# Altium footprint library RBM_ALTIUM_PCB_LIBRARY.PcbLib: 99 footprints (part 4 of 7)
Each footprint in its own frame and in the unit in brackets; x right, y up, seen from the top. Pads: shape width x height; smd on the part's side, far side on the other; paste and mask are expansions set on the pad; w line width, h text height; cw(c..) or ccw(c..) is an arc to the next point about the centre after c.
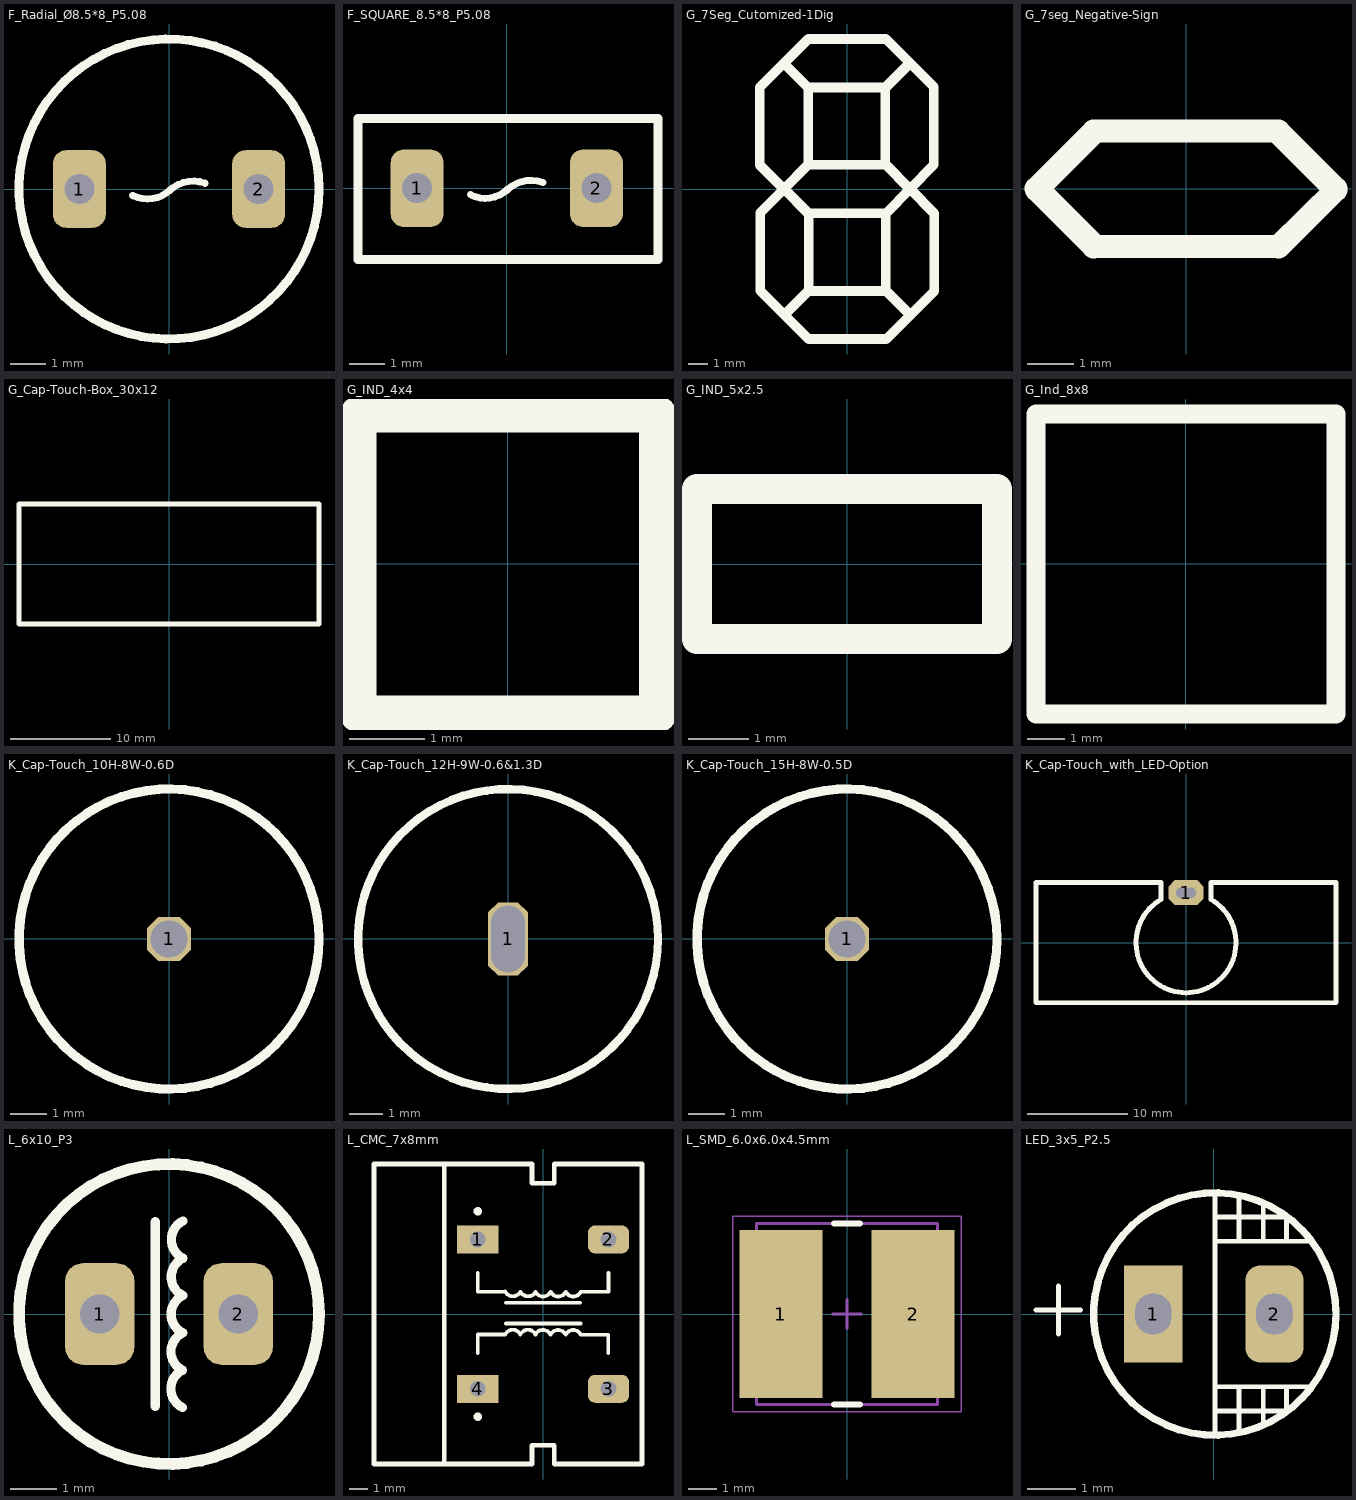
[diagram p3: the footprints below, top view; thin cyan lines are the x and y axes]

## F_Radial_Ø8.5*8_P5.08 [mm] "37011000000; Through Hole,P=5.08mm Fuses with Leads (Through Hole) RoHS"
pads (2):
  rrect50% 1.5x2.2 hole 0.85: 1(-2.54,0) 2(2.54,0)
Top Overlay:
  lines w0.2: -1.028,-0.184 ccw(c-0.609,0.633) 0.034,-0.022 ; 0.001,-0.057 cw(c0.685,-0.753) 1.023,0.162
  lines w0.254: 4.25,0 cw(c0,0) 4.25,0.019
3D body "User Library-Fuísivel 37200500411.step": height 8, standoff -4.3, extent -4.25,-4.25 4.25,4.25

## F_SQUARE_8.5*8_P5.08 [mm] "Littelfuse 39211000440; TE5 Time-Lag Fuse"
pads (2):
  rrect50% 1.5x2.2 hole 0.85: 1(-2.54,0) 2(2.54,0)
Top Overlay:
  lines w0.2: -1.028,-0.184 ccw(c-0.609,0.633) 0.034,-0.022 ; 0.001,-0.057 cw(c0.685,-0.753) 1.023,0.162
  lines w0.254: -4.216,-2.022 4.284,-2.022 4.284,1.978 -4.216,1.978 -4.216,-2.022
3D body "User Library-A3D-008-00001.step": height 8, standoff -3, extent -4.216,-2.022 4.284,1.978

## G_7Seg_Cutomized-1Dig [mm]
Top Overlay:
  lines w0.5: -4.475,1.237 -3.237,0 ; -3.263,0 -4.5,1.237 -4.5,5.237 -3.263,6.475 ; -3.237,6.5 -2,7.737 2,7.737 3.237,6.5 4.475,5.263 4.475,1.263 3.237,0.025 ; -3.212,-6.475 -1.975,-5.237 2.025,-5.237 3.263,-6.475 ; -3.212,-6.45 -1.975,-5.212 -1.975,-1.212 -3.212,0.025 ; -2,-7.687 -3.237,-6.45 -4.475,-5.212 -4.475,-1.212 -3.237,0.025 ; -2,-1.212 -3.237,0.025 ; -2,7.712 -3.237,6.475 ; -1.975,-7.712 2.025,-7.712 3.263,-6.475 ; 3.212,0.025 1.975,1.263 1.975,5.263 3.212,6.5 ; 3.237,-6.475 2,-5.237 2,-1.237 ; 3.237,6.475 2,5.237 -2,5.237 ; 3.263,0 4.5,-1.237 4.5,-5.237 3.263,-6.475 ; 4.475,-1.237 3.237,0 ; -3.237,0 -2,-1.237 2,-1.237 ; -3.237,0 -2,1.237 ; -3.237,0 -2,1.237 ; -3.237,0.025 -2,1.263 2,1.263 ; -3.237,6.475 -2,5.237 ; -3.237,6.475 -2,5.237 ; -2,1.237 -2,5.237 ; 2,-1.237 3.237,0 ; 2,-1.237 3.237,0 ; 2,1.263 3.237,0.025 ; 2,1.263 3.237,0.025
3D body: height 8, standoff 0, extent -3.511,-0.238 -1.767,1.506
3D body: height 8, standoff 0, extent -3.515,-1.478 -1.772,0.265
3D body: height 8, standoff 0, extent 1.748,-1.487 3.492,0.257
3D body: height 8, standoff 0, extent -2.25,1 2.238,1.5
3D body: height 8, standoff 0, extent 1.753,-0.247 3.497,1.497
3D body: height 8, standoff 0, extent -2.25,-1.5 2.238,-1
3D body: height 8, standoff 0, extent 1.759,-0.305 3.503,1.439
3D body: height 8, standoff 0, extent 3,-0.309 4.743,1.435
3D body: height 8, standoff 0, extent 3.008,4.954 4.752,6.698
3D body: height 8, standoff 0, extent 1.765,0.956 2.265,5.444
3D body: height 8, standoff 0, extent 1.768,4.959 3.511,6.703
3D body: height 8, standoff 0, extent 4.265,0.956 4.765,5.444
3D body: height 8, standoff 0, extent 1.757,-6.711 3.501,-4.967
3D body: height 8, standoff 0, extent 2.997,-6.715 4.741,-4.972
3D body: height 8, standoff 0, extent 3.006,-1.452 4.749,0.292
3D body: height 8, standoff 0, extent 1.763,-5.45 2.263,-0.962
3D body: height 8, standoff 0, extent 1.765,-1.447 3.509,0.297
3D body: height 8, standoff 0, extent 4.263,-5.45 4.763,-0.962
3D body: height 8, standoff 0, extent 1.773,-7.956 3.517,-6.212
3D body: height 8, standoff 0, extent 1.778,-6.715 3.522,-4.971
3D body: height 8, standoff 0, extent -3.486,-6.707 -1.742,-4.963
3D body: height 8, standoff 0, extent -2.232,-7.95 2.256,-7.45
3D body: height 8, standoff 0, extent -3.49,-7.947 -1.747,-6.203
3D body: height 8, standoff 0, extent -2.232,-5.45 2.256,-4.95
3D body: height 8, standoff 0, extent -3.466,-1.433 -1.722,0.311
3D body: height 8, standoff 0, extent -4.706,-1.428 -2.963,0.315
3D body: height 8, standoff 0, extent -4.715,-6.692 -2.971,-4.948
3D body: height 8, standoff 0, extent -2.228,-5.438 -1.728,-0.95
3D body: height 8, standoff 0, extent -3.475,-6.697 -1.731,-4.953
3D body: height 8, standoff 0, extent -4.728,-5.438 -4.228,-0.95
3D body: height 8, standoff 0, extent -3.494,4.967 -1.75,6.711
3D body: height 8, standoff 0, extent -4.735,4.972 -2.991,6.715
3D body: height 8, standoff 0, extent -4.743,-0.292 -2.999,1.452
3D body: height 8, standoff 0, extent -2.256,0.962 -1.756,5.45
3D body: height 8, standoff 0, extent -3.503,-0.297 -1.759,1.447
3D body: height 8, standoff 0, extent -4.756,0.962 -4.256,5.45
3D body: height 8, standoff 0, extent 1.767,4.994 3.511,6.738
3D body: height 8, standoff 0, extent 1.772,6.235 3.515,7.978
3D body: height 8, standoff 0, extent -3.492,6.243 -1.748,7.987
3D body: height 8, standoff 0, extent -2.238,5 2.25,5.5
3D body: height 8, standoff 0, extent -3.497,5.003 -1.753,6.747
3D body: height 8, standoff 0, extent -2.238,7.5 2.25,8

## G_7seg_Negative-Sign [mm]
Top Overlay:
  lines w0.5: -3.237,0 -2,1.237 ; -3.212,0 -1.975,-1.237 ; -2,-1.263 -3.237,-0.025 -2,1.212 ; 1.975,1.237 3.212,0 ; 2,-1.263 3.25,-0.025 ; 2,-1.25 -2,-1.25 -3.25,0 -2,1.25 2,1.25 3.25,0 ; 2,1.237 3.237,0
3D body: height 8, standoff 0, extent 1.767,-1.506 3.511,0.238
3D body: height 8, standoff 0, extent 1.772,-0.265 3.515,1.478
3D body: height 8, standoff 0, extent -3.492,-0.257 -1.748,1.487
3D body: height 8, standoff 0, extent -2.238,-1.5 2.25,-1
3D body: height 8, standoff 0, extent -3.497,-1.497 -1.753,0.247
3D body: height 8, standoff 0, extent -2.244,1 2.244,1.5

## G_Cap-Touch-Box_30x12 [mm]
Top Overlay:
  lines w0.5: -15,-6 15,-6 15,6 -15,6 -15,-6
3D body: height 8, standoff 0, extent -15.25,-6.206 -14.75,6.207
3D body: height 8, standoff 0, extent -15.206,-6.25 15.207,-5.75
3D body: height 8, standoff 0, extent 14.75,-6.206 15.25,6.207
3D body: height 8, standoff 0, extent -15.206,5.75 15.207,6.25

## G_IND_4x4 [mm]
Top Overlay:
  lines w0.5: -2,-2 -2,2 2,2 2,-2 -2,-2
3D body: height 8, standoff 0, extent -2.256,1.75 2.257,2.25
3D body: height 8, standoff 0, extent -2.25,-2.257 -1.75,2.256
3D body: height 8, standoff 0, extent -2.263,-2.25 2.25,-1.75
3D body: height 8, standoff 0, extent 1.75,-2.256 2.25,2.257

## G_IND_5x2.5 [mm]
Top Overlay:
  lines w0.5: -2.506,-1.244 -2.506,1.256 2.494,1.256 2.494,-1.244 -2.506,-1.244
3D body: height 8, standoff 0, extent 2.244,-1.48 2.744,1.492
3D body: height 8, standoff 0, extent -2.74,-1.494 2.727,-0.994
3D body: height 8, standoff 0, extent -2.756,-1.48 -2.256,1.492
3D body: height 8, standoff 0, extent -2.739,1.006 2.728,1.506

## G_Ind_8x8 [mm]
Top Overlay:
  lines w0.5: -3.994,-4.006 4.006,-4.006 4.006,3.994 -3.994,3.994 -3.994,-4.006
3D body: height 8, standoff 0, extent 3.756,-4.241 4.256,4.229
3D body: height 8, standoff 0, extent -4.229,-4.256 4.241,-3.756
3D body: height 8, standoff 0, extent -4.244,-4.241 -3.744,4.228
3D body: height 8, standoff 0, extent -4.228,3.744 4.241,4.244

## K_Cap-Touch_10H-8W-0.6D [mm]
pads (1):
  oct 1.2x1.2 / inner oct 1x1 / far side oct 2.5x2.5 hole 1: 1(0,0)
Top Overlay:
  circle w0.254: c0,0 r4.09
3D body: height 3, standoff -3, extent -0.258,-0.259 0.26,0.26
3D body: height 10, standoff 0, extent -4,-3.997 4,3.997

## K_Cap-Touch_12H-9W-0.6&1.3D [mm]
pads (1):
  oct 1.2x2.2 / inner oct 1x1 / far side oct 3x3 hole 2 slot 1 at 0 deg: 1(0,0)
Top Overlay:
  circle w0.254: c0,0 r4.5
3D body: height 12, standoff 0, extent -4.5,-4.5 4.5,4.5
3D body: height 5, standoff -3, extent -0.3,-0.7 0.3,0.7

## K_Cap-Touch_15H-8W-0.5D [mm]
pads (1):
  oct 1.2x1.2 / inner oct 1x1 / far side oct 2.5x2.5 hole 1: 1(0,0)
Top Overlay:
  circle w0.254: c0,0 r4.09
3D body: height 3, standoff -3, extent -0.258,-0.259 0.26,0.26
3D body: height 15, standoff 0, extent -4,-3.997 4,3.997

## K_Cap-Touch_with_LED-Option [mm]
pads (1):
  oct 3.5x2.5 hole 2 slot 1 at 90 deg: 1(0,5)
Top Overlay:
  lines w0.5: -15,-6 15,-6 15,6 2.5,6 2.5,4.33 cw(c0,0) -2.5,4.33 -2.5,6 -15,6 -15,-6
3D body "Touch_Spring.STEP": height 11.25, standoff -2.76, extent -5.25,-5.25 5.25,5.25

## L_6x10_P3 [mm]
pads (2):
  rrect50% 1.5x2.2 hole 0.85: 1(-1.5,0) 2(1.5,0)
Top Overlay:
  circle w0.254: c0,0 r3.25
  lines w0.2: -0.3,-2 -0.3,2 ; 0.293,-2.025 cw(c0.489,-1.622) 0.295,-1.217 cw(c0.492,-0.813) 0.298,-0.408 cw(c0.494,-0.005) 0.3,0.4 cw(c0.497,0.804) 0.302,1.208 cw(c0.499,1.612) 0.305,2.017
3D body: height 11.5, standoff 0.5, extent -2.993,-3.07 3.006,2.93
3D body: height 3.25, standoff 0.25, extent -3.242,-3.316 3.258,3.177
3D body: height 13, standoff 10, extent -3.242,-3.316 3.258,3.177
3D body: height 2, standoff -1, extent -1.799,-0.299 -1.201,0.299
3D body: height 2, standoff -1, extent 1.202,-0.299 1.8,0.3

## L_CMC_7x8mm [mm] "UU9.8"
pads (4):
  rect 2.2x1.5 hole 0.85: 1(-3.501,3.996) 4(-3.501,-4.004)
  rrect50% 2.2x1.5 hole 0.85: 2(3.499,3.996) 3(3.499,-4.004)
Top Overlay:
  lines w0.2: -3.501,-2.104 -3.501,-1.096 -2.026,-1.096 cw(c-1.622,-1.293) -1.218,-1.099 cw(c-0.814,-1.296) -0.409,-1.101 cw(c-0.006,-1.298) 0.399,-1.104 cw(c0.803,-1.3) 1.208,-1.106 cw(c1.611,-1.303) 2.016,-1.109 3.487,-1.109 3.487,-2.104 ; -3.501,2.196 -3.501,1.189 -2.035,1.189 -2.022,1.201 ccw(c-1.618,1.395) -1.214,1.199 ccw(c-0.809,1.393) -0.406,1.196 ccw(c-0.001,1.391) 0.403,1.194 ccw(c0.808,1.388) 1.211,1.191 ccw(c1.616,1.386) 2.02,1.189 3.487,1.189 3.499,1.201 3.499,2.196 ; -2.006,0.596 1.994,0.596 ; -2.001,-0.504 1.999,-0.504
  lines w0.254: -5.3,-8 -5.3,8 ; -3.401,-5.516 cw(c-3.5,-5.5) -3.4,-5.5 ; -3.401,5.484 cw(c-3.5,5.5) -3.4,5.5 ; -9.06,-8.033 -0.6,-8.033 -0.6,-7.033 0.598,-7.033 0.598,-8.033 5.3,-8.033 5.3,8.033 0.598,8.033 0.598,7 -0.6,7 -0.6,8.033 -9.06,8.033 -9.06,-8.033
3D body "User Library-UF9_8_H-1.step": height 12, standoff -2.5, extent -9.06,-8.033 5.3,8.033

## L_SMD_6.0x6.0x4.5mm [mm] "YNR6045-102M;  1mH ±20% 300mA 4.5O SMD,6.0x6.0x4.5mm Power Inductors RoHS"
height 4.5
pads (2):
  rect 2.9x5.85 smd: 1(-2.3,0) 2(2.3,0)
Top Overlay:
  lines w0.2: -0.45,-3.15 0.45,-3.15 ; -0.45,3.15 0.45,3.15
Assembly Top:
  lines w0.1: -3.15,-3.15 3.15,-3.15 3.15,3.15 -3.15,3.15 -3.15,-3.15
Courtyard Top:
  lines w0.05: -3.975,-3.4 3.975,-3.4 3.975,3.4 -3.975,3.4 -3.975,-3.4
  lines w0.1: -0.5,0 0.5,0 ; 0,-0.5 0,0.5
3D body "INDP6060X45N.step": height 4.6, standoff 0, extent -3.1,-3 3.1,3

## LED_3x5_P2.5 [mm]
pads (2):
  rect 1.2x2 hole 0.85 slot 0.75 at 0 deg: 1(-1.25,0)
  rrect50% 1.2x2 hole 0.85 slot 0.75 at 0 deg: 2(1.25,0)
Top Overlay:
  circle w0.15: c0.02,0 r2.5
  lines w0.1: -3.67,0.083 -2.754,0.083 ; -3.203,-0.417 -3.203,0.583 ; 0.02,-2.5 0.02,2.5 ; 0.02,-2 1.5,-2 1.5,-1.5 ; 0.02,-1.5 2.014,-1.5 ; 0.02,1.5 2.014,1.5 ; 0.02,2 1.5,2 1.5,1.5 ; 0.52,-2.4 0.52,-1.5 ; 0.52,1.5 0.52,2.4 ; 1.02,-2.3 1.02,-1.5 ; 1.02,1.5 1.02,2.3
3D body "LED_3x5_P2.5.STEP": height 7.38, standoff -1.17, extent -1.974,-1.498 2.014,1.994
